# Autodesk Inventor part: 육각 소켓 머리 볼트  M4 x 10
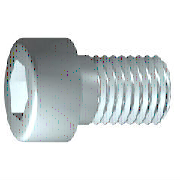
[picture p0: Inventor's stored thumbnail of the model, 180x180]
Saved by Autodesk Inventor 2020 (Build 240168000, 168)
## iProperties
Created: 2012-02
Part Number: 육각 소켓 머리 볼트  M4 x 10
Material: 스테인리스강
Description: 6각 소켓 머리 캡 나사
Document SubType Name: Modeling
Standard: ISO 4762
Designer: mdu-01
Standard Revision: Fourth edition 2004-03-01
Standards Organization: ISO
Language: ko-KR
Size Designation: M4 x 10
Categories: <MemberInstance><Categories><Category DisplayName="조임쇠" InternalName="e4da775c-781d-43d5-af7c-5136215cf5a6" Mnemonic="FSTN"><Category DisplayName="볼트" InternalN
Density: 7.75 g/cm^3
Appearance: 반광택
IsCustomPart: 1
Author: mdu-01
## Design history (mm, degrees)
sketch "스케치1"
  geometry: L1 (-1, 0)-(10, 0); L2 (10, 0)-(10, 2); L3 (10, 2)-(1.75, 2); L4 (1.75, 2)-(1.32, 2); L5 (1.32, 2)-(0, 2); L6 (0, 2)-(0, 3.5); L7 (0, 3.5)-(-4, 3.5); L8 (-4, 3.5)-(-4, 1.732); L9 (-4, 1.732)-(-2, 1.732); L10 (-2, 1.732)-(-1, 0); L11 (-6.8, 0)-(12.8, 0) reference; L12 (0, -0.7)-(0, 4.2) reference; L13 (1.75, 2)-(0, 2)
  constraints: 22 end point, 6 parallel, 2 collinear, 2 perpendicular, 1 horizontal, 1 point on line
  dimensions: "d1" = 8.25 distance from line of L3.end L2 (= GEL); "d2" = 0.42952 distance of L4.end L3.end (computed from GAL); "d3" = 4 distance between parallel lines of L8 L6 (= KOH); "d4" = 2 distance of L8.end L9.end (= INTI); "d5" = 60 deg angle of L10 L1; "d6" = 4 diameter of L3 L1 (= GD); "d7" = 4 diameter of L5 L1 (= BDM); "d8" = 3.4641 diameter of L9 L1 (= 1.1547 x SW); "d9" = 7 diameter of L7 L1 (= KOD); "d26" = 10 distance between parallel lines of L12 L2 (= NLG)
revolve "본체" sketch "스케치1" stored, may be unused: angle "d10" = 90 deg
sketch "스케치2"
  geometry: L1 (0, -4.9)-(0, 4.9) reference; L2 (-4.9, 0)-(4.9, 0) reference; L3 (1.732, 0)-(0.866, -1.5); L4 (0.866, -1.5)-(-0.866, -1.5); L5 (-0.866, -1.5)-(-1.732, 0); L6 (-1.732, 0)-(-0.866, 1.5); L7 (-0.866, 1.5)-(0.866, 1.5); L8 (0.866, 1.5)-(1.732, 0); 2 further points
  constraints: 12 end point, 1 coincident, 1 horizontal alignment, 1 point on line, 12 other
extrude "슬롯" join sketch "스케치2" stored distance "d11" = 10; taper "d12" = 0 deg
workplane "Work Plane1"
fillet "Fillet2" dims "d30" = 0.1 (= R)
body "Solid1"
fillet "모깎기1" dims "d17" = 0.4 (= RR)
feature "스레드" dims "d13" = 8.25 (= GEL), "d14" = 0
chamfer "모따기1" distance "d15" = 0.42941 (= -0.5 x SPD + 0.5 x GD); stored, may be unused: second distance "d16" = 0.42941 (= GUL), angle "d27" = 45 deg
other parameters: "GD" = 4 [user parameter; used in 2 equation terms], "NLG" = 10 [user parameter; used in 1 equation term], "GEL" = 8.25 [user parameter; used in 2 equation terms], "KOD" = 7 [user parameter; used in 1 equation term], "KOH" = 4 [user parameter; used in 1 equation term], "INTI" = 2 [user parameter; used in 1 equation term], "GAL" = 0.42941 (= 0.61345 x PTC) [user parameter; used in 1 equation term], "GUL" = 0.42941 (= 0.61345 x PTC) [user parameter; used in 1 equation term], "BDM" = 4 (= NND) [user parameter; used in 1 equation term], "SW" = 3 [user parameter; used in 2 equation terms], "RR" = 0.4 [user parameter; used in 1 equation term], "SPD" = 3.14117 (= NND - 1.2269 x PTC) [user parameter; used in 1 equation term], "d19" = 0, "d28" = 0, "d29" = 0, "R" = 0.1 [user parameter; used in 1 equation term], "TOA" = 30 deg [user parameter], "GD1" = 3.14117 (= THREADDIA - 1.2269 x PTC) [user parameter], "THREADDIA" = 4 [user parameter; used in 1 equation term], "FAWI" = 45 deg [user parameter], "TPU" = 14.28571 (computed from PTC) [user parameter], "PTC" = 0.7 [user parameter; used in 5 equation terms], "NND" = 4 [user parameter; used in 2 equation terms], "E0" = 3.465 (= 1.155 x SW) [user parameter]
